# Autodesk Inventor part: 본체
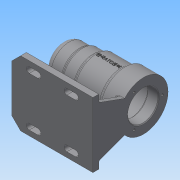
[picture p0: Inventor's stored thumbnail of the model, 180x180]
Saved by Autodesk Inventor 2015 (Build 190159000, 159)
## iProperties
Created: 2017-09
Part Number: 본체
Material: 일반
Document SubType Name: Modeling
Designer: owner
Density: 1 g/cm^3
Appearance: 기본값
Author: owner
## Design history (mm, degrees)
sketch "스케치3"
  geometry: L1 (0, 0)-(112, 0); L2 (112, 0)-(112, 34); L3 (112, 34)-(84, 34); L4 (84, 34)-(84, 30); L5 (84, 30)-(45, 30); L6 (45, 30)-(45, 27); L7 (45, 27)-(25, 27); L8 (25, 27)-(25, 25); L9 (25, 25)-(0, 25); L10 (0, 25)-(0, 0)
  constraints: 20 end point, 6 perpendicular, 2 horizontal, 2 vertical
  dimensions: "d5" = 112 distance of L1.start L1.end; "d6" = 25 distance between parallel lines of L8 L10; "d7" = 45 distance between parallel lines of L6 L10; "d9" = 84 distance between parallel lines of L4 L10; "d10" = 50 diameter of L9 L1; "d11" = 54 diameter of L7 L1; "d12" = 60 diameter of L5 L1; "d13" = 68 diameter of L3 L1
revolve "회전1" sketch "스케치3" stored, may be unused: angle "d14" = 90 deg
sketch "스케치4"
  geometry: L1 (112, -34)-(112, 34) reference; L2 (0, 0)-(112, 0); L3 (0, 0)-(0, -60); L4 (0, -60)-(22, -60); L5 (22, -60)-(38.077, 0); L6 (22, -60)-(84.117, -60); L7 (38.077, 0)-(112, 0); L8 (112, 0)-(112, -60); L9 (22, -60)-(112, -60); L10 (112, -60)-(112, -62)
  constraints: 18 end point, 3 horizontal, 3 vertical, 2 midpoint, 1 equal length, 1 perpendicular
  dimensions: "d15" = 60 distance of L2.start L3.end; "d16" = 22 distance of L3.end L4.end; "d17" = 75 deg angle of L6 L5; "d18" = 60 distance of L7.end L8.end; "d100" = 2 distance of L8.end L10.end
extrude "돌출1" join sketch "스케치4" stored distance "d19" = 8; taper "d20" = 0 deg
sketch "스케치5"
  geometry: L1 (0, 0)-(0, 26.236) reference; L2 (8, 0)-(0, 0) reference; L3 (8, 26.236)-(8, 0) reference; L4 (4, 26)-(4, 0); L5 (4, 0)-(4, -2); L6 (4, -2)-(39, -2); L7 (39, -2)-(25.9, 33.992); A1 r 34 centre (4, 60) between (8, 26.236) and (0, 26.236) reference; A2 r 34 centre (4, 60) between (4, 26) and (25.9, 33.992)
  constraints: 9 end point, 2 point on circle, 1 centre point, 1 coincident, 1 horizontal, 1 midpoint, 1 parallel, 1 vertical
  dimensions: "d21" = 60 distance of A1.centre L4.end; "d24" = 34 radius of A2; "d97" = 2 distance of L4.end L5.end; "d98" = 35 distance of L5.end L6.end; "d99" = 110 deg angle of L6 L7
extrude "돌출2" join sketch "스케치5" distance "d26" = 8; taper "d27" = 0 deg
sketch "스케치9"
  geometry: C1 r 21 at (0, 0); A1 r 34 centre (0, 0) between (21.9, -26.008) and (-21.9, -26.008) reference; 2 further points
  constraints: 1 centre point, 1 coincident
  dimensions: "d34" = 42 diameter of C1
extrude "돌출4" cut sketch "스케치9" distance "d35" = 15; taper "d36" = 0 deg
sketch "스케치12"
  geometry: C1 r 21 at (0, 0) reference; C2 r 24 at (0, 0)
  constraints: 1 centre point, 1 coincident
  dimensions: "d41" = 48 diameter of C2
extrude "돌출6" cut sketch "스케치12" distance "d42" = 54; taper "d43" = 0 deg
sketch "스케치13"
  geometry: C1 r 24 at (0, 0) reference; C2 r 21 at (0, 0)
  constraints: 1 centre point, 1 coincident
  dimensions: "d44" = 42 diameter of C2
extrude "돌출7" cut sketch "스케치13" distance "d45" = 12; taper "d46" = 0 deg
sketch "스케치14"
  geometry: C1 r 21 at (0, 0) reference; C2 r 17.5 at (0, 0)
  constraints: 1 centre point, 1 coincident
  dimensions: "d47" = 35 diameter of C2
extrude "돌출8" cut sketch "스케치14" distance "d48" = 18; taper "d49" = 0 deg
sketch "스케치15"
  geometry: C1 r 17.5 at (0, 0) reference; C2 r 16 at (0, 0)
  constraints: 1 centre point, 1 coincident
  dimensions: "d50" = 32 diameter of C2
extrude "돌출9" cut sketch "스케치15" distance "d51" = 4; taper "d52" = 0 deg
sketch "스케치16"
  geometry: C1 r 16 at (0, 0) reference; C2 r 10.5 at (0, 0)
  constraints: 1 centre point, 1 coincident
  dimensions: "d53" = 21 diameter of C2
extrude "돌출10" cut sketch "스케치16" distance "d54" = 3; taper "d55" = 0 deg
node "작업 평면3"
sketch "스케치21"
  geometry: L1 (47.5, 21)-(47.5, -21) reference; 2 further points
  constraints: 1 other
  dimensions: "d71" = 0 vertical distance of point (-0.5, 0) point (-64.5, 0); "d72" = 48 distance from line of L1 point (-0.5, 0)
feature "엠보싱1" sketch "스케치21" dims "d73" = 0.5, "d74" = 0
sketch "스케치22" dims "d75" = 52
  geometry: L1 (0, 0)-(0, 26); A1 r 34 centre (0, 0) between (21.9, -26.008) and (-21.9, -26.008) reference; 3 further points
  constraints: 2 coincident, 2 end point, 1 vertical, 1 vertical alignment, 2 other
hole "구멍1" sketch "스케치22" at (0, 26) diameter "d76" = 3.242; stored, may be unused: countersink angle "d80" = 90 deg, drill point angle "d82" = 118 deg; dims "d77" = 8, "d78" = 4, "d79" = 2, "d81" = 11
chamfer "모따기1" distance "d86" = 1; stored, may be unused: second distance "d87" = 2, angle "d88" = 45 deg
fillet "모깎기1" dims "d92" = 0.3
fillet "모깎기2" dims "d93" = 9
fillet "모깎기3" dims "d94" = 3
fillet "모깎기4" dims "d95" = 3
fillet "모깎기5" dims "d96" = 3
sketch "스케치24"
  geometry: L1 (75.894, 0)-(0, 0) reference; L2 (78.894, 11)-(78.894, -3) reference; L3 (0, 8)-(75.894, 8) reference; L4 (-3.106, 5)-(-3.106, 3) reference; L5 (78.894, 4)-(78.894, 8); L6 (78.894, 8)-(-3.106, 8); L7 (-3.106, 4)-(-3.106, 8); L8 (-3.106, 4)-(-3.106, 0); L9 (-3.106, 0)-(78.894, 0); L10 (78.894, 0)-(78.894, 8); A1 r 3 centre (75.894, -3) between (78.894, -3) and (75.894, 0) reference; A2 r 3 centre (75.894, 11) between (75.894, 8) and (78.894, 11) reference; 3 further points; 2 other entities
  constraints: 12 end point, 3 vertical, 2 midpoint, 2 perpendicular, 2 point on line, 2 other
  dimensions: "d101" = 4 distance of L5.start L5.end; "d102" = 4 distance of L7.start L8.end
extrude "돌출12" join sketch "스케치24" distance "d103" = 2; taper "d104" = 0 deg
fillet "모깎기6" dims "d105" = 3
sketch "스케치25"
  geometry: L1 (8, 70)-(8, 0) reference; L2 (8, 35)-(8, 80); L3 (8, 80)-(-104, 80); L4 (-104, 80)-(-104, -10); L5 (-104, -10)-(8, -10); L6 (8, -10)-(8, 35); 1 further point
  constraints: 10 end point, 2 perpendicular, 1 collinear, 1 midpoint, 1 point on line, 1 vertical
  dimensions: "d106" = 45 distance of L2.start L2.end; "d107" = 112 distance of L2.end L3.end; "d108" = 90 distance of L3.end L4.end; "d109" = 112 distance of L4.end L5.end
extrude "돌출13" join sketch "스케치25" distance "d110" = 8; taper "d111" = 0 deg
sketch "스케치27"
  geometry: L1 (8, -70)-(8, -80) reference; L2 (-28, -69)-(-16, -69); L3 (-28, -73)-(-16, -73); L4 (-16, -65)-(-28, -65); A1 r 4 centre (-28, -69) between (-28, -65) and (-28, -73); A2 r 4 centre (-16, -69) between (-16, -73) and (-16, -65); 2 further points
  constraints: 8 end point, 4 point on circle, 4 tangent, 2 centre point, 1 horizontal, 1 midpoint, 1 parallel
  dimensions: "d112" = 6 distance of point (-22, -69) L2.end; "d113" = 8 diameter of A2; "d114" = 34 distance from line of L2 point (-104, -35); "d115" = 24 distance from line of L1 L2.end
extrude "돌출14" cut sketch "스케치27" stored distance "d116" = 8; taper "d117" = 0 deg
chamfer "모따기3" distance "d121" = 12; stored, may be unused: second distance "d122" = 2, angle "d123" = 45 deg
fillet "모깎기8" dims "d125" = 3
fillet "모깎기9" dims "d126" = 3
fillet "모깎기10" dims "d127" = 3
node "솔리드1"
mirror "대칭1"
pattern_circular "원형 패턴1" dims angle "d84" = 360 deg
pattern_linear "직사각형 패턴3" dims "d120" = 52
mirror "대칭3"
node "작업 평면1"
node "작업 평면4"
